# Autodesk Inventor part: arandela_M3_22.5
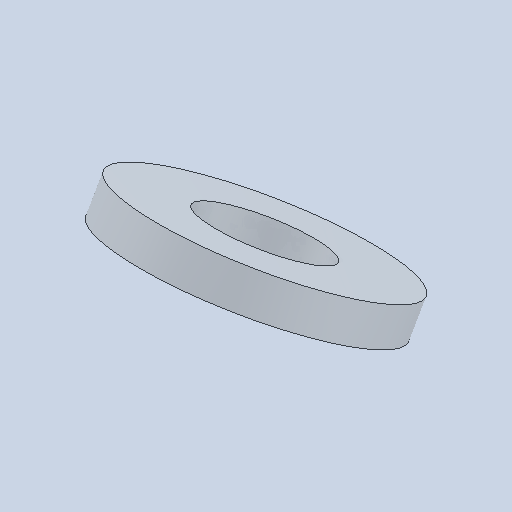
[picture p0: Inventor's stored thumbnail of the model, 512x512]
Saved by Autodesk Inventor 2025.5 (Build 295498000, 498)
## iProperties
Created: 2026-10
Part Number: arandela_M3_22.5
Material: Genérico
Document SubType Name: Modeling
Designer: Luis M
Density: 1 g/cm^3
Appearance: Valor por defecto
Author: Luis M
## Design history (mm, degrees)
feature "Base1"
node "Sólido1"
